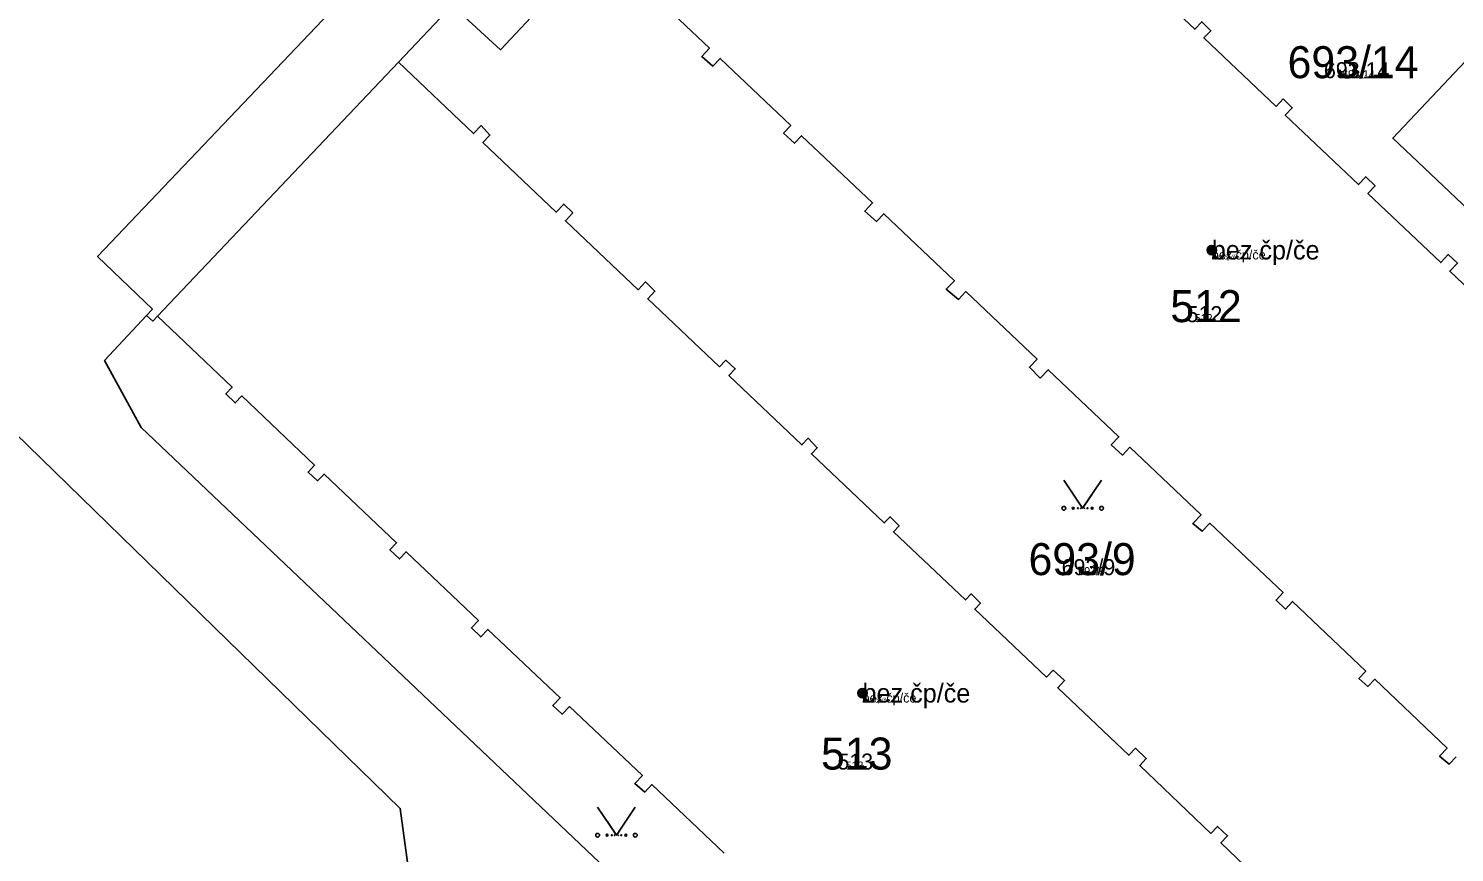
# Model space of a CAD drawing. Extents: x -744652 to -739090, y -980828 to -975855.
# Drawn here: x -743707.2 to -743631.5, y -978268.3 to -978224.5 of the extents above; entities that cross this region are included whole.
import ezdxf

# ---------------------------------------------------------------- set-up
doc = ezdxf.new("R2010")
doc.units = 0
for name, color, linetype in [('KAT_02_hranice parcel', 7, 'Continuous'), ('KAT_03_1000_st čísla parcelní', 7, 'Continuous'), ('KAT_03_1000_čísla parcelní', 7, 'Continuous'), ('KAT_03_1000_čísla popisná', 7, 'Continuous'), ('KAT_03_100_st čísla parcelní', 7, 'Continuous'), ('KAT_03_100_čísla parcelní', 7, 'Continuous'), ('KAT_03_100_čísla popisná', 7, 'Continuous'), ('KAT_03_250_st čísla parcelní', 7, 'Continuous'), ('KAT_03_250_čísla parcelní', 7, 'Continuous'), ('KAT_03_250_čísla popisná', 7, 'Continuous'), ('KAT_03_500_st čísla parcelní', 7, 'Continuous'), ('KAT_03_500_čísla parcelní', 7, 'Continuous'), ('KAT_03_500_čísla popisná', 7, 'Continuous'), ('KAT_05_1000_značky kultur', 7, 'Continuous'), ('KAT_05_100_značky kultur', 7, 'Continuous'), ('KAT_05_250_značky kultur', 7, 'Continuous'), ('KAT_05_500_značky kultur', 7, 'Continuous'), ('KAT_07_1000_značky budov', 7, 'Continuous'), ('KAT_07_100_značky budov', 7, 'Continuous'), ('KAT_07_500_značky budov', 7, 'Continuous'), ('KAT_14_plocha_budovy', 7, 'Continuous')]:
    doc.layers.add(name, color=color, linetype=linetype)

msp = doc.modelspace()

# ---------------------------------------------------------------- linework, layer by layer
at = {"layer": 'KAT_02_hranice parcel'}
msp.add_line((-743687.58, -978226.28), (-743700.38, -978239.77), dxfattribs=at)
for points in [[(-743700.96, -978239.74), (-743700.65, -978239.4), (-743703.56, -978236.6), (-743668.78, -978200.04), (-743676.86, -978192.88)], [(-743620.41, -978198.76), (-743613.94, -978208.23), (-743634.77, -978230.31), (-743602.97, -978260.44), (-743595.47, -978260.11), (-743595.57, -978264.25), (-743596.53, -978265.95), (-743598.73, -978267.87), (-743605.1, -978261.83)], [(-743687.58, -978226.28), (-743684.73, -978223.27), (-743682.16, -978225.62), (-743679.73, -978223.03), (-743682.28, -978220.69), (-743679.39, -978217.64)], [(-743627.88, -978241.05), (-743631.74, -978237.38), (-743631.33, -978236.95), (-743631.82, -978236.5), (-743632.22, -978236.93), (-743636.09, -978233.25), (-743635.71, -978232.85), (-743636.2, -978232.37), (-743636.59, -978232.78), (-743640.48, -978229.09), (-743640.11, -978228.7), (-743640.59, -978228.23), (-743640.97, -978228.63), (-743644.8, -978224.99), (-743644.43, -978224.61), (-743644.91, -978224.13), (-743645.29, -978224.53), (-743649.17, -978220.84)], [(-743674.87, -978221.93), (-743671.06, -978225.54), (-743671.47, -978225.97), (-743670.88, -978226.49), (-743670.49, -978226.08), (-743666.74, -978229.65), (-743667.12, -978230.05), (-743666.55, -978230.59), (-743666.17, -978230.19), (-743662.4, -978233.76), (-743662.81, -978234.19), (-743662.19, -978234.75), (-743661.8, -978234.33), (-743658.05, -978237.89), (-743658.48, -978238.34), (-743657.84, -978238.89), (-743657.44, -978238.47), (-743653.66, -978242.05), (-743654.07, -978242.48), (-743653.49, -978243.06), (-743653.07, -978242.62), (-743649.31, -978246.18), (-743649.72, -978246.61), (-743649.12, -978247.15), (-743648.73, -978246.74), (-743644.95, -978250.32), (-743645.39, -978250.78), (-743644.89, -978251.2), (-743644.48, -978250.77), (-743640.59, -978254.46), (-743640.97, -978254.86), (-743640.47, -978255.33), (-743640.09, -978254.93), (-743636.2, -978258.63), (-743636.57, -978259.02), (-743636.09, -978259.44), (-743635.73, -978259.06), (-743631.88, -978262.72), (-743632.28, -978263.14), (-743631.78, -978263.58), (-743631.4, -978263.18)], [(-743640.11, -978271.38), (-743643.9, -978267.76), (-743643.54, -978267.38), (-743644.07, -978266.88), (-743644.43, -978267.25), (-743648.21, -978263.64), (-743647.86, -978263.27), (-743648.43, -978262.73), (-743648.78, -978263.1), (-743652.56, -978259.51), (-743652.2, -978259.13), (-743652.81, -978258.58), (-743653.16, -978258.95), (-743656.97, -978255.33), (-743656.67, -978255.02), (-743657.16, -978254.53), (-743657.47, -978254.85), (-743661.29, -978251.23), (-743660.99, -978250.91), (-743661.47, -978250.43), (-743661.78, -978250.76), (-743665.65, -978247.09), (-743665.34, -978246.76), (-743665.82, -978246.26), (-743666.15, -978246.61), (-743670.03, -978242.93), (-743669.69, -978242.57), (-743670.19, -978242.11), (-743670.53, -978242.46), (-743674.34, -978238.85), (-743673.96, -978238.45), (-743674.45, -978237.95), (-743674.84, -978238.37), (-743678.71, -978234.7), (-743678.32, -978234.29), (-743678.8, -978233.82), (-743679.2, -978234.24), (-743683.09, -978230.54), (-743682.72, -978230.15), (-743683.19, -978229.65), (-743683.59, -978230.07), (-743687.58, -978226.28)], [(-743639.49, -978298.13), (-743640.65, -978299.06), (-743643.52, -978298.82), (-743646.29, -978297.86), (-743701.24, -978245.69), (-743703.19, -978242.13), (-743700.96, -978239.74)], [(-743700.96, -978239.74), (-743700.62, -978240.03), (-743700.38, -978239.77)], [(-743700.38, -978239.77), (-743696.41, -978243.54), (-743696.75, -978243.9), (-743696.25, -978244.38), (-743695.9, -978244.01), (-743692.03, -978247.69), (-743692.38, -978248.06), (-743691.88, -978248.52), (-743691.53, -978248.16), (-743687.68, -978251.81), (-743688.03, -978252.18), (-743687.53, -978252.67), (-743687.17, -978252.29), (-743683.33, -978255.94), (-743683.7, -978256.33), (-743683.21, -978256.81), (-743682.83, -978256.41), (-743678.99, -978260.04), (-743679.38, -978260.45), (-743678.89, -978260.92), (-743678.5, -978260.51), (-743674.62, -978264.18), (-743675.02, -978264.6), (-743674.5, -978265.06), (-743674.12, -978264.66), (-743670.28, -978268.3)], [(-743688.32, -978278.13), (-743692.24, -978283.84), (-743695.51, -978280.98), (-743719.93, -978263.52), (-743744.09, -978287.8), (-743751.64, -978272.45), (-743750.38, -978264.67), (-743730.74, -978243.6), (-743726.49, -978242.07), (-743720.04, -978241.24), (-743716.26, -978241.05), (-743714.01, -978241.47), (-743711.81, -978242.57), (-743710.09, -978243.89), (-743687.48, -978265.92), (-743686.65, -978272.04), (-743688.32, -978278.13)]]:
    msp.add_lwpolyline(points, dxfattribs=at)
at = {"layer": 'KAT_03_1000_čísla popisná'}
for centre in [(-743644.38, -978236.26), (-743644.38, -978236.26), (-743662.93, -978259.8), (-743662.93, -978259.8)]:
    msp.add_circle(centre, 0.25, dxfattribs=at)
at = {"layer": 'KAT_03_100_čísla popisná'}
for centre in [(-743644.38, -978236.26), (-743644.38, -978236.26), (-743662.93, -978259.8), (-743662.93, -978259.8)]:
    msp.add_circle(centre, 0.025, dxfattribs=at)
at = {"layer": 'KAT_03_250_čísla popisná'}
for centre in [(-743644.38, -978236.26), (-743644.38, -978236.26), (-743662.93, -978259.8), (-743662.93, -978259.8)]:
    msp.add_circle(centre, 0.0625, dxfattribs=at)
at = {"layer": 'KAT_03_500_čísla popisná'}
for centre in [(-743644.38, -978236.26), (-743644.38, -978236.26), (-743662.93, -978259.8), (-743662.93, -978259.8)]:
    msp.add_circle(centre, 0.125, dxfattribs=at)
at = {"layer": 'KAT_05_1000_značky kultur'}
for points in [[(-743652.24, -978248.479), (-743651.24, -978249.98), (-743650.24, -978248.479)], [(-743677, -978265.849), (-743676, -978267.35), (-743675, -978265.849)]]:
    msp.add_lwpolyline(points, dxfattribs=at)
for centre in [(-743652.24, -978249.979), (-743650.24, -978249.979), (-743677, -978267.349), (-743675, -978267.349)]:
    msp.add_circle(centre, 0.1, dxfattribs=at)
at = {"layer": 'KAT_05_100_značky kultur'}
for points in [[(-743651.34, -978249.83), (-743651.24, -978249.98), (-743651.14, -978249.83)], [(-743676.1, -978267.2), (-743676, -978267.35), (-743675.9, -978267.2)]]:
    msp.add_lwpolyline(points, dxfattribs=at)
for centre in [(-743651.34, -978249.98), (-743651.14, -978249.98), (-743676.1, -978267.35), (-743675.9, -978267.35)]:
    msp.add_circle(centre, 0.01, dxfattribs=at)
at = {"layer": 'KAT_05_250_značky kultur'}
for points in [[(-743651.49, -978249.605), (-743651.24, -978249.98), (-743650.99, -978249.605)], [(-743676.25, -978266.975), (-743676, -978267.35), (-743675.75, -978266.975)]]:
    msp.add_lwpolyline(points, dxfattribs=at)
for centre in [(-743651.49, -978249.98), (-743650.99, -978249.98), (-743676.25, -978267.35), (-743675.75, -978267.35)]:
    msp.add_circle(centre, 0.025, dxfattribs=at)
at = {"layer": 'KAT_05_500_značky kultur'}
for points in [[(-743651.74, -978249.23), (-743651.24, -978249.98), (-743650.74, -978249.23)], [(-743676.5, -978266.6), (-743676, -978267.35), (-743675.5, -978266.6)]]:
    msp.add_lwpolyline(points, dxfattribs=at)
for centre in [(-743651.74, -978249.98), (-743650.74, -978249.98), (-743676.5, -978267.35), (-743675.5, -978267.35)]:
    msp.add_circle(centre, 0.05, dxfattribs=at)
at = {"layer": 'KAT_07_1000_značky budov'}
for centre in [(-743644.387, -978236.259), (-743662.937, -978259.799)]:
    msp.add_circle(centre, 0.175, dxfattribs=at)
at = {"layer": 'KAT_07_100_značky budov'}
for centre in [(-743644.381, -978236.26), (-743662.931, -978259.8)]:
    msp.add_circle(centre, 0.0175, dxfattribs=at)
at = {"layer": 'KAT_07_500_značky budov'}
for centre, radius in [((-743644.383, -978236.26), 0.0875), ((-743644.382, -978236.26), 0.0438), ((-743662.933, -978259.8), 0.0875), ((-743662.932, -978259.8), 0.0438)]:
    msp.add_circle(centre, radius, dxfattribs=at)
at = {"layer": 'KAT_14_plocha_budovy'}
for points in [[(-743668.78, -978200.04), (-743703.56, -978236.6), (-743700.65, -978239.4), (-743700.96, -978239.74), (-743700.62, -978240.03), (-743700.38, -978239.77), (-743687.58, -978226.28), (-743684.73, -978223.27), (-743682.16, -978225.62), (-743679.73, -978223.03)], [(-743627.88, -978241.05), (-743631.74, -978237.38), (-743631.33, -978236.95), (-743631.82, -978236.5), (-743632.22, -978236.93), (-743636.09, -978233.25), (-743635.71, -978232.85), (-743636.2, -978232.37), (-743636.59, -978232.78), (-743640.48, -978229.09), (-743640.11, -978228.7), (-743640.59, -978228.23), (-743640.97, -978228.63), (-743644.8, -978224.99), (-743644.43, -978224.61), (-743644.91, -978224.13), (-743645.29, -978224.53), (-743649.17, -978220.84)], [(-743674.87, -978221.93), (-743671.06, -978225.54), (-743671.47, -978225.97), (-743670.88, -978226.49), (-743670.49, -978226.08), (-743666.74, -978229.65), (-743667.12, -978230.05), (-743666.55, -978230.59), (-743666.17, -978230.19), (-743662.4, -978233.76), (-743662.81, -978234.19), (-743662.19, -978234.75), (-743661.8, -978234.33), (-743658.05, -978237.89), (-743658.48, -978238.34), (-743657.84, -978238.89), (-743657.44, -978238.47), (-743653.66, -978242.05), (-743654.07, -978242.48), (-743653.49, -978243.06), (-743653.07, -978242.62), (-743649.31, -978246.18), (-743649.72, -978246.61), (-743649.12, -978247.15), (-743648.73, -978246.74), (-743644.95, -978250.32), (-743645.39, -978250.78), (-743644.89, -978251.2), (-743644.48, -978250.77), (-743640.59, -978254.46), (-743640.97, -978254.86), (-743640.47, -978255.33), (-743640.09, -978254.93), (-743636.2, -978258.63), (-743636.57, -978259.02), (-743636.09, -978259.44), (-743635.73, -978259.06), (-743631.88, -978262.72), (-743632.28, -978263.14), (-743631.78, -978263.58), (-743631.4, -978263.18)], [(-743687.58, -978226.28), (-743700.38, -978239.77), (-743696.41, -978243.54), (-743696.75, -978243.9), (-743696.25, -978244.38), (-743695.9, -978244.01), (-743692.03, -978247.69), (-743692.38, -978248.06), (-743691.88, -978248.52), (-743691.53, -978248.16), (-743687.68, -978251.81), (-743688.03, -978252.18), (-743687.53, -978252.67), (-743687.17, -978252.29), (-743683.33, -978255.94), (-743683.7, -978256.33), (-743683.21, -978256.81), (-743682.83, -978256.41), (-743678.99, -978260.04), (-743679.38, -978260.45), (-743678.89, -978260.92), (-743678.5, -978260.51), (-743674.62, -978264.18), (-743675.02, -978264.6), (-743674.5, -978265.06), (-743674.12, -978264.66), (-743670.28, -978268.3)], [(-743674.34, -978238.85), (-743673.96, -978238.45), (-743674.45, -978237.95), (-743674.84, -978238.37), (-743678.71, -978234.7), (-743678.32, -978234.29), (-743678.8, -978233.82), (-743679.2, -978234.24), (-743683.09, -978230.54), (-743682.72, -978230.15), (-743683.19, -978229.65), (-743683.59, -978230.07), (-743687.58, -978226.28)], [(-743640.11, -978271.38), (-743643.9, -978267.76), (-743643.54, -978267.38), (-743644.07, -978266.88), (-743644.43, -978267.25), (-743648.21, -978263.64), (-743647.86, -978263.27), (-743648.43, -978262.73), (-743648.78, -978263.1), (-743652.56, -978259.51), (-743652.2, -978259.13), (-743652.81, -978258.58), (-743653.16, -978258.95), (-743656.97, -978255.33), (-743656.67, -978255.02), (-743657.16, -978254.53), (-743657.47, -978254.85), (-743661.29, -978251.23), (-743660.99, -978250.91), (-743661.47, -978250.43), (-743661.78, -978250.76), (-743665.65, -978247.09), (-743665.34, -978246.76), (-743665.82, -978246.26), (-743666.15, -978246.61), (-743670.03, -978242.93), (-743669.69, -978242.57), (-743670.19, -978242.11), (-743670.53, -978242.46), (-743674.34, -978238.85)]]:
    msp.add_lwpolyline(points, dxfattribs=at)

# ---------------------------------------------------------------- texts
at = {"layer": 'KAT_03_1000_st čísla parcelní'}
for s, p in [('512', (-743646.584, -978240.09)), ('513', (-743665.134, -978263.86))]:
    msp.add_text(s, height=1.7, dxfattribs=at).set_placement(p)
at = {"layer": 'KAT_03_1000_čísla parcelní'}
for s, p in [('693/14', (-743640.355, -978227.13)), ('693/9', (-743654.113, -978253.53))]:
    msp.add_text(s, height=1.7, dxfattribs=at).set_placement(p)
at = {"layer": 'KAT_03_1000_čísla popisná'}
for s, height, p in [('bez čp/če', 1, (-743644.38, -978236.76)), ('512', 0.017, (-743644.875, -978240.09)), ('bez čp/če', 1, (-743662.93, -978260.3)), ('513', 0.017, (-743663.411, -978263.86))]:
    msp.add_text(s, height=height, dxfattribs=at).set_placement(p)
at = {"layer": 'KAT_03_100_st čísla parcelní'}
for s, p in [('512', (-743645.03, -978240.09)), ('513', (-743663.568, -978263.86))]:
    msp.add_text(s, height=0.17, dxfattribs=at).set_placement(p)
at = {"layer": 'KAT_03_100_čísla parcelní'}
for s, p in [('693/14', (-743636.88, -978227.13)), ('693/9', (-743650.945, -978253.53))]:
    msp.add_text(s, height=0.17, dxfattribs=at).set_placement(p)
at = {"layer": 'KAT_03_100_čísla popisná'}
for s, height, p in [('bez čp/če', 0.1, (-743644.38, -978236.76)), ('512', 0.0017, (-743644.859, -978240.09)), ('bez čp/če', 0.1, (-743662.93, -978260.3)), ('513', 0.0017, (-743663.396, -978263.86))]:
    msp.add_text(s, height=height, dxfattribs=at).set_placement(p)
at = {"layer": 'KAT_03_250_st čísla parcelní'}
for s, p in [('512', (-743645.289, -978240.09)), ('513', (-743663.829, -978263.86))]:
    msp.add_text(s, height=0.425, dxfattribs=at).set_placement(p)
at = {"layer": 'KAT_03_250_čísla parcelní'}
for s, p in [('693/14', (-743637.459, -978227.13)), ('693/9', (-743651.473, -978253.53))]:
    msp.add_text(s, height=0.425, dxfattribs=at).set_placement(p)
at = {"layer": 'KAT_03_250_čísla popisná'}
for s, height, p in [('bez čp/če', 0.25, (-743644.38, -978236.76)), ('512', 0.00425, (-743644.862, -978240.09)), ('bez čp/če', 0.25, (-743662.93, -978260.3)), ('513', 0.00425, (-743663.398, -978263.86))]:
    msp.add_text(s, height=height, dxfattribs=at).set_placement(p)
at = {"layer": 'KAT_03_500_st čísla parcelní'}
for s, p in [('512', (-743645.721, -978240.09)), ('513', (-743664.264, -978263.86))]:
    msp.add_text(s, height=0.85, dxfattribs=at).set_placement(p)
at = {"layer": 'KAT_03_500_čísla parcelní'}
for s, p in [('693/14', (-743638.424, -978227.13)), ('693/9', (-743652.353, -978253.53))]:
    msp.add_text(s, height=0.85, dxfattribs=at).set_placement(p)
at = {"layer": 'KAT_03_500_čísla popisná'}
for s, height, p in [('bez čp/če', 0.5, (-743644.38, -978236.76)), ('512', 0.0085, (-743644.866, -978240.09)), ('bez čp/če', 0.5, (-743662.93, -978260.3)), ('513', 0.0085, (-743663.403, -978263.86))]:
    msp.add_text(s, height=height, dxfattribs=at).set_placement(p)

doc.saveas('drawing.dxf')
